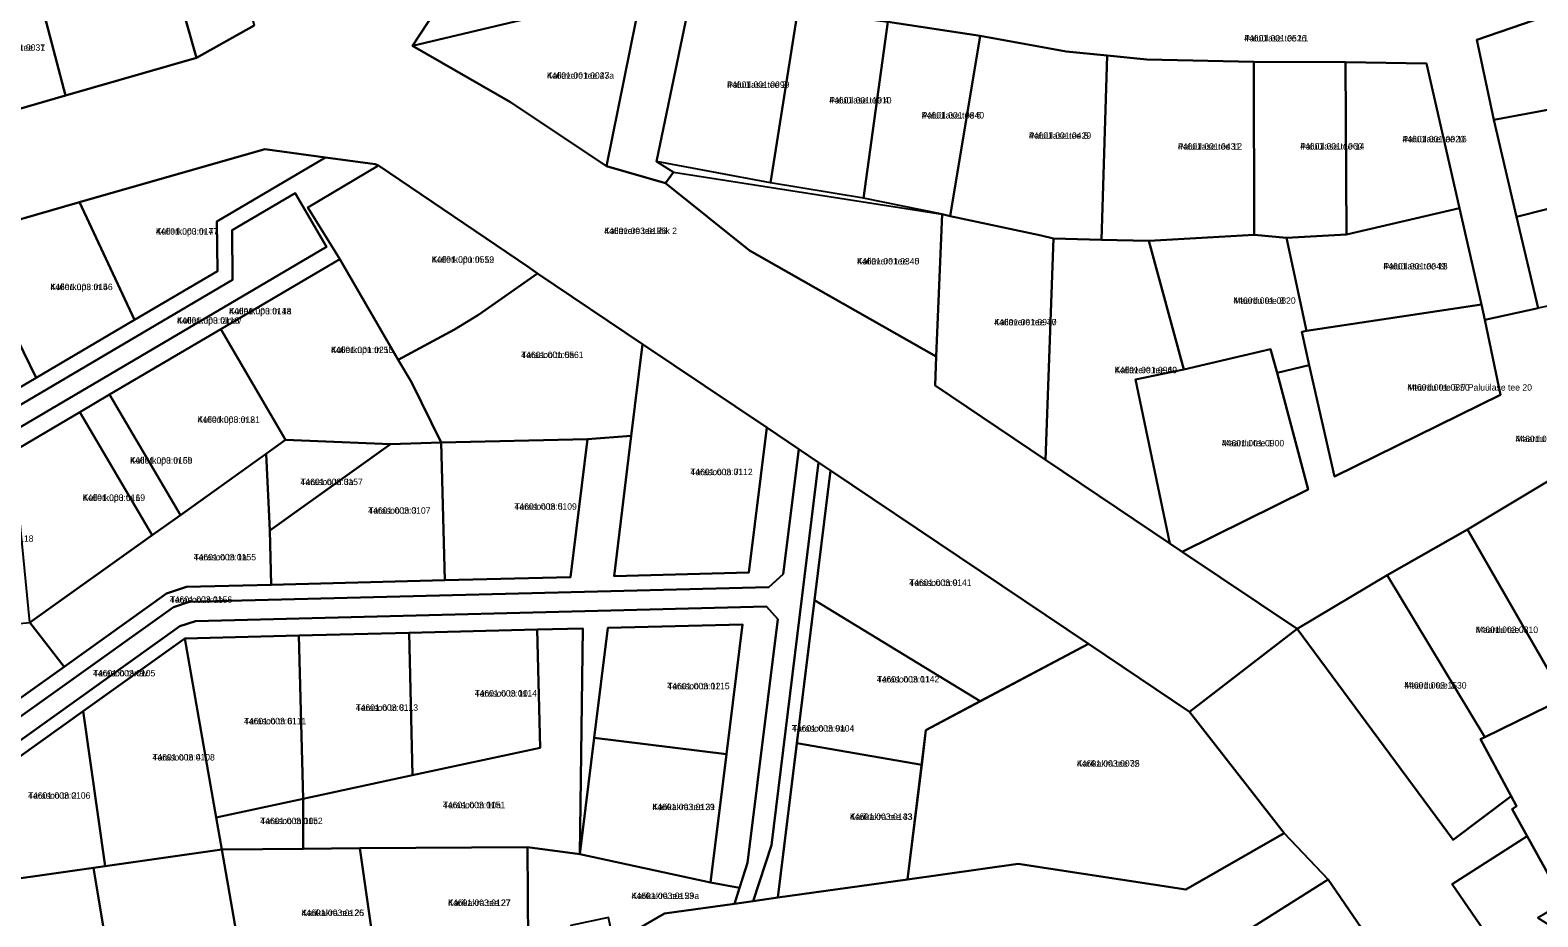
# Model space of a CAD drawing. Extents: x 551843 to 558501, y 6589003 to 6595718.
# Drawn here: x 553189.3 to 553540.1, y 6594024.1 to 6594230.4 of the extents above; entities that cross this region are included whole.
import ezdxf

# ---------------------------------------------------------------- set-up
doc = ezdxf.new("R2010")
doc.units = 0
for name, color, linetype in [('L_AADRESS', 7, 'Continuous'), ('PIIR', 7, 'Continuous'), ('TUNNUS', 7, 'Continuous')]:
    doc.layers.add(name, color=color, linetype=linetype)

msp = doc.modelspace()

# ---------------------------------------------------------------- linework, layer by layer
at = {"layer": 'PIIR'}
for points in [[(553182.49, 6594330.12), (553232.4, 6594326.2), (553240.38, 6594325.59), (553262.8, 6594322.38), (553279.95, 6594314.8), (553298.4, 6594300.69), (553308.9, 6594287.55), (553287.18, 6594294.2), (553279.07, 6594300.71), (553277.07, 6594302.32), (553259.01, 6594310.9), (553245.86, 6594313.49), (553198.74, 6594312.55), (553190.02, 6594301.54), (553212.52, 6594279.48), (553234.07, 6594258.36), (553235.92, 6594251.62), (553241.45, 6594231.48), (553228.02, 6594223.98), (553220.49, 6594250.55), (553194.56, 6594276.53), (553173.93, 6594295.82)], [(553293.82, 6594250.57), (553278.23, 6594226.81), (553301.09, 6594213.65), (553323.4, 6594198.76), (553337.12, 6594194.86), (553356.68, 6594179.16), (553400.1, 6594154.47), (553399.83, 6594147.77), (553425.56, 6594130.46), (553454.47, 6594111.02), (553457.35, 6594109.1), (553484.11, 6594091.16), (553459.04, 6594071.81), (553435.51, 6594087.64), (553375.53, 6594127.99), (553372.76, 6594129.85), (553368.11, 6594132.98), (553360.67, 6594137.98), (553331.8, 6594157.38), (553307.35, 6594173.84), (553305.16, 6594175.33), (553270.34, 6594198.91), (553269.54, 6594199.28), (553258.04, 6594200.83), (553243.88, 6594202.74), (553200.76, 6594190.38), (553174.39, 6594182.82)], [(553343.01, 6594238.32), (553335.02, 6594199.88), (553338.95, 6594197.37), (553337.12, 6594194.86), (553323.4, 6594198.76), (553331.6, 6594239.47), (553278.23, 6594226.81), (553293.82, 6594250.57)], [(553573.56, 6594244.65), (553525.91, 6594228.2), (553529.84, 6594209.6), (553535.15, 6594187), (553540.14, 6594165.77), (553527.74, 6594163.06), (553527, 6594166.59), (553521.82, 6594189.04), (553514.16, 6594222.65), (553495.37, 6594222.96), (553473.98, 6594223.08), (553449.14, 6594223.63), (553439.92, 6594224.57), (553430.37, 6594225.43), (553410.34, 6594229.12), (553388.89, 6594232.33)], [(553168.38, 6594206.76), (553197.54, 6594215.23), (553228.02, 6594223.98), (553241.45, 6594231.48)], [(553182.94, 6594144.94), (553190.73, 6594149.53), (553213.61, 6594163), (553232.86, 6594174.36), (553232.76, 6594185.89), (553258.04, 6594200.83), (553269.54, 6594199.28), (553270.34, 6594198.91), (553253.89, 6594189.18), (553261.33, 6594177.12), (553233.64, 6594160.85), (553207.76, 6594145.63), (553200.87, 6594141.57), (553185.36, 6594132.43)], [(553185.82, 6594137.34), (553258.29, 6594180.04), (553250.93, 6594192.53), (553236.28, 6594183.9), (553236.38, 6594172.37), (553184.39, 6594141.73)], [(553543.13, 6594125.92), (553523.71, 6594114.29), (553505.01, 6594103.63), (553484.11, 6594091.16), (553457.35, 6594109.1), (553486.67, 6594123.54), (553479.4, 6594150.67), (553486.9, 6594152.52), (553492.79, 6594126.56), (553531.43, 6594145.58), (553527.74, 6594163.06), (553540.14, 6594165.77)], [(553170.2, 6594053.25), (553224.15, 6594091.75), (553227.78, 6594092.96), (553360.6, 6594096.32), (553363.23, 6594093.42), (553356.24, 6594036.72), (553354.34, 6594030.87), (553347.62, 6594032.15), (553351.29, 6594062), (553355.01, 6594092.18), (553323.68, 6594091.39), (553320.53, 6594065.79), (553317.19, 6594038.71), (553317.91, 6594091.25), (553307.29, 6594090.98), (553277.46, 6594090.22), (553251.83, 6594089.57), (553225.32, 6594088.9), (553201.62, 6594071.99), (553170.89, 6594050.06)], [(553542.86, 6593955.37), (553538.17, 6593962.48), (553515.56, 6593997.37), (553491.31, 6594032.8), (553481.08, 6594043.63), (553459.04, 6594071.81), (553484.11, 6594091.16), (553520.41, 6594042.06), (553533.9, 6594052.21), (553535.15, 6594049.87), (553534.09, 6594049.22), (553537.6, 6594042.92), (553520.12, 6594031.76), (553552.16, 6593985.04)], [(553325.1, 6594018.08), (553336.89, 6594024.9), (553353.15, 6594027.19), (553357.56, 6594027.81), (553363.29, 6594028.62), (553393.45, 6594032.87), (553419.2, 6594036.5), (553458.17, 6594030.53), (553481.08, 6594043.63), (553491.31, 6594032.8), (553462.32, 6594014.51)]]:
    msp.add_lwpolyline(points, dxfattribs=at)
for points in [[(553220.49, 6594250.55), (553228.02, 6594223.98), (553197.54, 6594215.23), (553190.32, 6594242.77)], [(553164.44, 6594243.15), (553182.96, 6594241.12), (553190.32, 6594242.77), (553197.54, 6594215.23), (553168.38, 6594206.76), (553159, 6594242.47)], [(553573.56, 6594244.65), (553582.2, 6594219.28), (553579.53, 6594218.79), (553529.84, 6594209.6), (553525.91, 6594228.2)], [(553323.4, 6594198.76), (553301.09, 6594213.65), (553278.23, 6594226.81), (553331.6, 6594239.47)], [(553343.01, 6594238.32), (553367.9, 6594235.07), (553361.55, 6594194.88), (553335.02, 6594199.88)], [(553388.89, 6594232.33), (553383.16, 6594191.31), (553361.55, 6594194.88), (553367.9, 6594235.07)], [(553383.16, 6594191.31), (553388.89, 6594232.33), (553410.34, 6594229.12), (553403.39, 6594187.19), (553401.47, 6594187.63)], [(553403.39, 6594187.19), (553410.34, 6594229.12), (553430.37, 6594225.43), (553439.92, 6594224.57), (553438.6, 6594181.65), (553427.38, 6594181.98), (553424.51, 6594182.66)], [(553438.6, 6594181.65), (553439.92, 6594224.57), (553449.14, 6594223.63), (553473.98, 6594223.08), (553474.06, 6594182.85), (553452.38, 6594181.56), (553449.57, 6594181.43)], [(553474.06, 6594182.85), (553473.98, 6594223.08), (553495.37, 6594222.96), (553495.59, 6594182.89), (553481.64, 6594182.12)], [(553514.16, 6594222.65), (553521.82, 6594189.04), (553495.59, 6594182.89), (553495.37, 6594222.96)], [(553529.84, 6594209.6), (553579.53, 6594218.79), (553583.92, 6594199.32), (553535.15, 6594187)], [(553200.76, 6594190.38), (553243.88, 6594202.74), (553258.04, 6594200.83), (553232.76, 6594185.89), (553232.86, 6594174.36), (553213.61, 6594163)], [(553261.33, 6594177.12), (553253.89, 6594189.18), (553270.34, 6594198.91), (553305.16, 6594175.33), (553307.35, 6594173.84), (553293.63, 6594164.23), (553288, 6594160.75), (553274.94, 6594153.74)], [(553356.68, 6594179.16), (553337.12, 6594194.86), (553338.95, 6594197.37), (553401.47, 6594187.63), (553400.1, 6594154.47)], [(553583.92, 6594199.32), (553589.08, 6594176.48), (553540.14, 6594165.77), (553535.15, 6594187)], [(553136.18, 6594136.22), (553180.68, 6594140.52), (553184.39, 6594141.73), (553236.38, 6594172.37), (553236.28, 6594183.9), (553250.93, 6594192.53), (553258.29, 6594180.04), (553185.82, 6594137.34), (553182.1, 6594136.13), (553136.92, 6594131.77)], [(553174.39, 6594182.82), (553200.76, 6594190.38), (553213.61, 6594163), (553190.73, 6594149.53)], [(553400.1, 6594154.47), (553401.47, 6594187.63), (553403.39, 6594187.19), (553424.51, 6594182.66), (553427.38, 6594181.98), (553425.56, 6594130.46), (553399.83, 6594147.77)], [(553495.59, 6594182.89), (553521.82, 6594189.04), (553527, 6594166.59), (553486.24, 6594160.48), (553481.64, 6594182.12)], [(553156.91, 6594177.81), (553174.39, 6594182.82), (553190.73, 6594149.53), (553182.94, 6594144.94), (553179.96, 6594143.97), (553162.86, 6594142.32)], [(553457.74, 6594151.5), (553449.57, 6594181.43), (553452.38, 6594181.56), (553474.06, 6594182.85), (553481.64, 6594182.12), (553486.24, 6594160.48), (553485.16, 6594160.22), (553486.9, 6594152.52), (553479.4, 6594150.67), (553477.92, 6594156.2)], [(553454.47, 6594111.02), (553425.56, 6594130.46), (553427.38, 6594181.98), (553438.6, 6594181.65), (553449.57, 6594181.43), (553457.74, 6594151.5), (553446.46, 6594149.13)], [(553248.74, 6594135.14), (553233.64, 6594160.85), (553261.33, 6594177.12), (553274.94, 6594153.74), (553278, 6594148.56), (553284.96, 6594134.47), (553273.18, 6594134.12)], [(553278, 6594148.56), (553274.94, 6594153.74), (553288, 6594160.75), (553293.63, 6594164.23), (553307.35, 6594173.84), (553331.8, 6594157.38), (553329.14, 6594136.05), (553318.99, 6594135.27), (553284.96, 6594134.47)], [(553486.24, 6594160.48), (553527, 6594166.59), (553527.74, 6594163.06), (553531.43, 6594145.58), (553492.79, 6594126.56), (553486.9, 6594152.52), (553485.16, 6594160.22)], [(553207.76, 6594145.63), (553233.64, 6594160.85), (553248.74, 6594135.14), (553224.26, 6594117.63)], [(553331.8, 6594157.38), (553360.67, 6594137.98), (553356.49, 6594104.23), (553325.16, 6594103.44), (553329.14, 6594136.05)], [(553457.74, 6594151.5), (553477.92, 6594156.2), (553479.4, 6594150.67), (553486.67, 6594123.54), (553457.35, 6594109.1), (553454.47, 6594111.02), (553446.46, 6594149.13)], [(553207.76, 6594145.63), (553224.26, 6594117.63), (553217.72, 6594112.96), (553200.87, 6594141.57)], [(553185.36, 6594132.43), (553200.87, 6594141.57), (553217.72, 6594112.96), (553189.2, 6594092.61)], [(553148.96, 6594059.92), (553164.54, 6594060.06), (553167.15, 6594060.9), (553197.18, 6594082.33), (553221.05, 6594099.37), (553225.65, 6594100.91), (553245.38, 6594101.41), (553285.76, 6594102.44), (553315.05, 6594103.18), (553318.99, 6594135.27), (553329.14, 6594136.05), (553325.16, 6594103.44), (553356.49, 6594104.23), (553360.67, 6594137.98), (553368.11, 6594132.98), (553364.52, 6594103.89), (553361.16, 6594100.84), (553226.29, 6594097.43), (553222.66, 6594096.22), (553168.74, 6594057.74), (553165.11, 6594056.56), (553149.54, 6594056.42)], [(553244.2, 6594131.85), (553248.74, 6594135.14), (553273.18, 6594134.12), (553245.06, 6594114.04)], [(553245.06, 6594114.04), (553273.18, 6594134.12), (553284.96, 6594134.47), (553285.76, 6594102.44), (553245.38, 6594101.41)], [(553284.96, 6594134.47), (553318.99, 6594135.27), (553315.05, 6594103.18), (553285.76, 6594102.44)], [(553149.54, 6594056.42), (553165.11, 6594056.56), (553168.74, 6594057.74), (553222.66, 6594096.22), (553226.29, 6594097.43), (553361.16, 6594100.84), (553364.52, 6594103.89), (553368.11, 6594132.98), (553372.76, 6594129.85), (553361.79, 6594040.85), (553357.56, 6594027.81), (553353.15, 6594027.19), (553356.24, 6594036.72), (553363.23, 6594093.42), (553360.6, 6594096.32), (553227.78, 6594092.96), (553224.15, 6594091.75), (553170.2, 6594053.25), (553166.57, 6594052.07), (553150.3, 6594051.92)], [(553189.2, 6594092.61), (553217.72, 6594112.96), (553224.26, 6594117.63), (553244.2, 6594131.85), (553245.06, 6594114.04), (553245.38, 6594101.41), (553225.65, 6594100.91), (553221.05, 6594099.37), (553197.18, 6594082.33)], [(553372.76, 6594129.85), (553375.53, 6594127.99), (553363.29, 6594028.62), (553357.56, 6594027.81), (553361.79, 6594040.85)], [(553375.53, 6594127.99), (553435.51, 6594087.64), (553410.33, 6594074.29), (553371.82, 6594097.83)], [(553546.27, 6594075.04), (553523.71, 6594114.29), (553543.13, 6594125.92), (553553.46, 6594108.51), (553551.74, 6594107.51), (553566.95, 6594081.08)], [(553527.74, 6594065.97), (553505.01, 6594103.63), (553523.71, 6594114.29), (553546.27, 6594075.04)], [(553505.01, 6594103.63), (553527.74, 6594065.97), (553526.78, 6594065.5), (553533.9, 6594052.21), (553520.41, 6594042.06), (553484.11, 6594091.16)], [(553371.82, 6594097.83), (553410.33, 6594074.29), (553397.73, 6594067.61), (553396.73, 6594059.51), (553367.72, 6594064.55)], [(553144.21, 6594088.27), (553165.81, 6594090.36), (553189.2, 6594092.61), (553197.18, 6594082.33), (553167.15, 6594060.9), (553164.54, 6594060.06), (553148.96, 6594059.92)], [(553323.68, 6594091.39), (553355.01, 6594092.18), (553351.29, 6594062), (553320.53, 6594065.79)], [(553201.62, 6594071.99), (553225.32, 6594088.9), (553232.61, 6594047.23), (553233.9, 6594039.85), (553206.78, 6594035.97)], [(553225.32, 6594088.9), (553251.83, 6594089.57), (553252.8, 6594051.59), (553232.61, 6594047.23)], [(553251.83, 6594089.57), (553277.46, 6594090.22), (553278.3, 6594057.09), (553252.8, 6594051.59)], [(553307.29, 6594090.98), (553317.91, 6594091.25), (553317.19, 6594038.71), (553305.04, 6594040.37), (553265.99, 6594040.09), (553252.84, 6594039.99), (553252.8, 6594051.59), (553278.3, 6594057.09), (553307.99, 6594063.49)], [(553277.46, 6594090.22), (553307.29, 6594090.98), (553307.99, 6594063.49), (553278.3, 6594057.09)], [(553397.73, 6594067.61), (553435.51, 6594087.64), (553459.04, 6594071.81), (553481.08, 6594043.63), (553458.17, 6594030.53), (553419.2, 6594036.5), (553393.45, 6594032.87)], [(553596.23, 6594083.84), (553600.85, 6594062.74), (553591.42, 6594026.8), (553546.1, 6594027.45), (553537.6, 6594042.92), (553534.09, 6594049.22), (553535.15, 6594049.87), (553533.9, 6594052.21), (553526.78, 6594065.5), (553527.74, 6594065.97), (553546.27, 6594075.04), (553566.95, 6594081.08), (553572.4, 6594082.6), (553594.49, 6594083.76)], [(553170.89, 6594050.06), (553201.62, 6594071.99), (553206.78, 6594035.97), (553204.02, 6594035.58), (553174.03, 6594031.28)], [(553320.53, 6594065.79), (553351.29, 6594062), (553347.62, 6594032.15), (553317.19, 6594038.71)], [(553367.72, 6594064.55), (553396.73, 6594059.51), (553393.45, 6594032.87), (553363.29, 6594028.62)], [(553232.61, 6594047.23), (553252.8, 6594051.59), (553252.84, 6594039.99), (553233.9, 6594039.85)], [(553520.12, 6594031.76), (553537.6, 6594042.92), (553546.1, 6594027.45), (553540.07, 6594023.91), (553579.37, 6593999.32), (553570.97, 6593997.38), (553552.16, 6593985.04)], [(553204.02, 6594035.58), (553206.78, 6594035.97), (553233.9, 6594039.85), (553239.36, 6594008.61), (553209.26, 6594004.3)], [(553233.9, 6594039.85), (553252.84, 6594039.99), (553265.99, 6594040.09), (553269.87, 6594012.98), (553239.36, 6594008.61)], [(553265.99, 6594040.09), (553305.04, 6594040.37), (553305.21, 6594018.04), (553269.87, 6594012.98)], [(553305.04, 6594040.37), (553317.19, 6594038.71), (553347.62, 6594032.15), (553354.34, 6594030.87), (553353.15, 6594027.19), (553336.89, 6594024.9), (553325.1, 6594018.08), (553323.9, 6594023.96), (553315.09, 6594022.14), (553316.89, 6594013.33), (553304.12, 6594005.94), (553305.21, 6594018.04)], [(553174.03, 6594031.28), (553204.02, 6594035.58), (553209.26, 6594004.3), (553179.27, 6594000.01)], [(553462.32, 6594014.51), (553491.31, 6594032.8), (553515.56, 6593997.37), (553498.23, 6593988.72), (553496.48, 6593987.84), (553478.8, 6593979.02), (553468.64, 6593973.95), (553466.45, 6593986.28), (553465, 6593996.18)]]:
    msp.add_lwpolyline(points, close=True, dxfattribs=at)

# ---------------------------------------------------------------- texts
at = {"layer": 'L_AADRESS'}
for s, p in [('Paluülase tee L1', (553471.75, 6594227.8)), ('Kallavere tee 37', (553178.27, 6594225.63)), ('Kallavere tee 43a', (553309.55, 6594219.12)), ('Paluülase tee 2', (553351.46, 6594217)), ('Paluülase tee 4', (553375.22, 6594213.37)), ('Paluülase tee 6', (553396.75, 6594209.87)), ('Paluülase tee 8', (553421.66, 6594205.15)), ('Paluülase tee 12', (553456.33, 6594202.63)), ('Paluülase tee 14', (553484.79, 6594202.66)), ('Paluülase tee 16', (553508.59, 6594204.34)), ('Kullerkupu tn 7', (553218.54, 6594182.87)), ('Kallavere tee lõik 2', (553322.86, 6594183)), ('Kullerkupu tn 12', (553282.74, 6594176.32)), ('Kallavere tee 45', (553381.68, 6594175.92)), ('Paluülase tee 18', (553504.16, 6594174.76)), ('Kullerkupu tn 5', (553194, 6594169.95)), ('Kullerkupu tn 1a', (553235.59, 6594164.32)), ('Maardu tee 3', (553469.24, 6594166.76)), ('Kullerkupu tänav', (553223.48, 6594162.15)), ('Kallavere tee 47', (553413.61, 6594161.75)), ('Kullerkupu tn 10', (553259.3, 6594155.31)), ('Tarasoo tn 5a', (553303.56, 6594154.15)), ('Kallavere tee 49', (553441.65, 6594150.61)), ('Maardu tee 5 // Paluülase tee 20', (553509.73, 6594146.57)), ('Kullerkupu tn 8', (553228.25, 6594139.08)), ('Maardu tee 1', (553466.57, 6594133.6)), ('Maardu tee lõik 1', (553534.9, 6594134.6)), ('Kullerkupu tn 6b', (553212.56, 6594129.59)), ('Tarasoo tn 7', (553342.91, 6594126.9)), ('Tarasoo tn 3a', (553252.19, 6594124.59)), ('Kullerkupu tn 6', (553201.54, 6594120.92)), ('Tarasoo tn 5', (553301.98, 6594118.86)), ('Tarasoo tn 3', (553267.95, 6594117.94)), ('Tarasoo tn 1a', (553227.36, 6594107.09)), ('Tarasoo tn 9', (553393.83, 6594101.14)), ('Tarasoo tn 1b', (553221.81, 6594097.2)), ('Maardu tee 4', (553525.64, 6594090.19)), ('Tarasoo tänav', (553203.93, 6594080.09)), ('Tarasoo tn 12', (553337.54, 6594077.09)), ('Tarasoo tn 11', (553386.31, 6594078.67)), ('Maardu tee 2', (553509, 6594077.25)), ('Tarasoo tn 10', (553292.73, 6594075.4)), ('Tarasoo tn 6', (553239.06, 6594068.94)), ('Tarasoo tn 8', (553265.06, 6594072.07)), ('Tarasoo tn 9a', (553366.55, 6594067.24)), ('Tarasoo tn 4', (553217.76, 6594060.52)), ('Karikakra tee 35', (553432.84, 6594059.09)), ('Tarasoo tn 2', (553188.82, 6594051.63)), ('Tarasoo tn 10a', (553285.35, 6594049.42)), ('Karikakra tee 31', (553334.07, 6594048.97)), ('Tarasoo tn 10c', (553242.85, 6594045.72)), ('Karikakra tee 33', (553380.01, 6594046.7)), ('Karikakra tee 29a', (553329.23, 6594028.29)), ('Karikakra tee 25', (553252.43, 6594024.35)), ('Karikakra tee 27', (553286.53, 6594026.68))]:
    msp.add_text(s, height=1.5, dxfattribs=at).set_placement(p)
at = {"layer": 'TUNNUS'}
for s, p in [('44601:001:0526', (553471.75, 6594227.8)), ('44601:001:0031', (553178.27, 6594225.63)), ('44601:001:0027', (553309.55, 6594219.12)), ('44601:001:0099', (553351.46, 6594217)), ('44601:001:1010', (553375.22, 6594213.37)), ('44601:001:0840', (553396.75, 6594209.87)), ('44601:001:0429', (553421.66, 6594205.15)), ('44601:001:0431', (553456.33, 6594202.63)), ('44601:001:1060', (553484.79, 6594202.66)), ('44601:001:0020', (553508.59, 6594204.34)), ('44601:003:0147', (553218.54, 6594182.87)), ('44601:003:0196', (553322.86, 6594183)), ('44601:001:0559', (553282.74, 6594176.32)), ('44601:001:0340', (553381.68, 6594175.92)), ('44601:001:0049', (553504.16, 6594174.76)), ('44601:003:0146', (553194, 6594169.95)), ('44601:003:0148', (553235.59, 6594164.32)), ('44601:001:0820', (553469.24, 6594166.76)), ('44601:003:0116', (553223.48, 6594162.15)), ('44601:001:0970', (553413.61, 6594161.75)), ('44601:001:0253', (553259.3, 6594155.31)), ('44601:001:0561', (553303.56, 6594154.15)), ('44601:001:0960', (553441.65, 6594150.61)), ('44601:001:0850', (553509.73, 6594146.57)), ('44601:003:0121', (553228.25, 6594139.08)), ('44601:001:0900', (553466.57, 6594133.6)), ('44601:003:0197', (553534.9, 6594134.6)), ('44601:003:0159', (553212.56, 6594129.59)), ('44601:003:0112', (553342.91, 6594126.9)), ('44601:003:0157', (553252.19, 6594124.59)), ('44601:003:0119', (553201.54, 6594120.92)), ('44601:003:0109', (553301.98, 6594118.86)), ('44601:003:0107', (553267.95, 6594117.94)), ('44601:003:0118', (553175.59, 6594111.39)), ('44601:003:0155', (553227.36, 6594107.09)), ('44601:003:0141', (553393.83, 6594101.14)), ('44601:003:0156', (553221.81, 6594097.2)), ('44601:003:0310', (553525.64, 6594090.19)), ('44601:003:0105', (553203.93, 6594080.09)), ('44601:003:0115', (553337.54, 6594077.09)), ('44601:003:0142', (553386.31, 6594078.67)), ('44601:003:1530', (553509, 6594077.25)), ('44601:003:0114', (553292.73, 6594075.4)), ('44601:003:0111', (553239.06, 6594068.94)), ('44601:003:0113', (553265.06, 6594072.07)), ('44601:003:0104', (553366.55, 6594067.24)), ('44601:003:0108', (553217.76, 6594060.52)), ('44601:003:0072', (553432.84, 6594059.09)), ('44601:003:0106', (553188.82, 6594051.63)), ('44601:003:0151', (553285.35, 6594049.42)), ('44601:003:0129', (553334.07, 6594048.97)), ('44601:003:0152', (553242.85, 6594045.72)), ('44601:003:0143', (553380.01, 6594046.7)), ('44601:003:0153', (553329.23, 6594028.29)), ('44601:003:0126', (553252.43, 6594024.35)), ('44601:003:0127', (553286.53, 6594026.68))]:
    msp.add_text(s, height=1.5, dxfattribs=at).set_placement(p)

doc.saveas('drawing.dxf')
